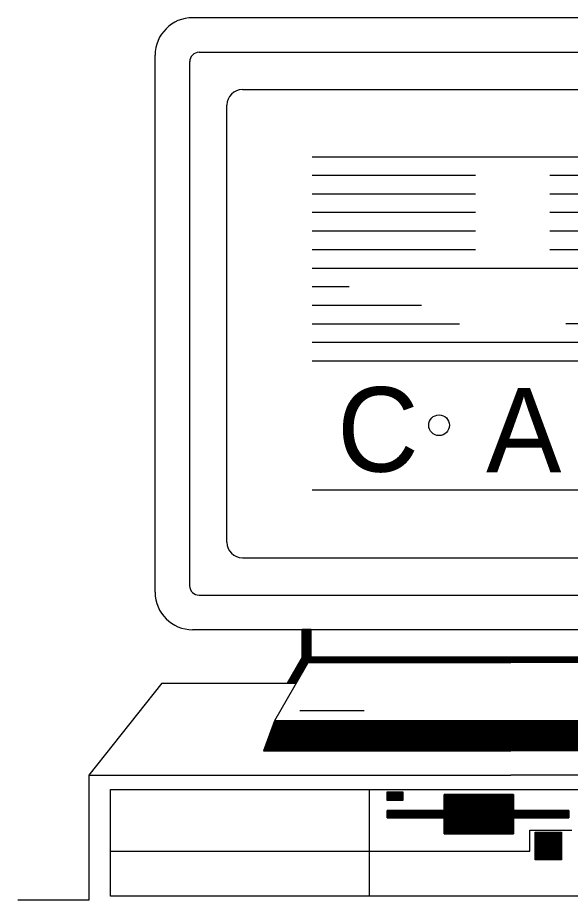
# Model space of a CAD drawing. Extents: x 22369.62 to 22376.4, y 22369.62 to 22372.46.
# Drawn here: x 22372.8189 to 22372.9001, y 22369.7337 to 22369.8633 of the extents above; entities that cross this region are included whole.
import ezdxf

# ---------------------------------------------------------------- set-up
doc = ezdxf.new("R2010")
doc.units = 0
for name, color, linetype in [('Level 2', 7, 'Continuous'), ('Level 25', 7, 'Continuous'), ('Level 3', 7, 'Continuous'), ('Level 5', 7, 'Continuous')]:
    doc.layers.add(name, color=color, linetype=linetype)

msp = doc.modelspace()

# ---------------------------------------------------------------- linework, layer by layer
at = {"layer": 'Level 2'}
for p, q in [((22372.85196, 22369.85273), (22372.93081, 22369.85273)), ((22372.84966, 22369.78628), (22372.84966, 22369.85044)), ((22372.85196, 22369.78399), (22372.93081, 22369.78399)), ((22372.86072, 22369.77334), (22372.86204, 22369.77334)), ((22372.86072, 22369.77327), (22372.86204, 22369.77327)), ((22372.86072, 22369.77318), (22372.86204, 22369.77318)), ((22372.86072, 22369.77309), (22372.86204, 22369.77309)), ((22372.86072, 22369.77301), (22372.86204, 22369.77301)), ((22372.86072, 22369.77294), (22372.86204, 22369.77294)), ((22372.86072, 22369.77285), (22372.86204, 22369.77285)), ((22372.86072, 22369.77276), (22372.86204, 22369.77276)), ((22372.86072, 22369.77268), (22372.86204, 22369.77268)), ((22372.86072, 22369.7726), (22372.86204, 22369.7726)), ((22372.86072, 22369.77252), (22372.86204, 22369.77252)), ((22372.86072, 22369.77244), (22372.86204, 22369.77244)), ((22372.86204, 22369.76941), (22372.86204, 22369.77346)), ((22372.86072, 22369.77235), (22372.86204, 22369.77235)), ((22372.86072, 22369.77227), (22372.86204, 22369.77227)), ((22372.86072, 22369.77219), (22372.86204, 22369.77219)), ((22372.86072, 22369.7721), (22372.86204, 22369.7721)), ((22372.86072, 22369.77203), (22372.86204, 22369.77203)), ((22372.86072, 22369.77194), (22372.86204, 22369.77194)), ((22372.86072, 22369.77185), (22372.86204, 22369.77185)), ((22372.86072, 22369.77178), (22372.86204, 22369.77178)), ((22372.86072, 22369.7717), (22372.86204, 22369.7717)), ((22372.86072, 22369.77161), (22372.86204, 22369.77161)), ((22372.86072, 22369.77152), (22372.86204, 22369.77152)), ((22372.86072, 22369.77145), (22372.86204, 22369.77145)), ((22372.86072, 22369.77136), (22372.86204, 22369.77136)), ((22372.86072, 22369.77128), (22372.86204, 22369.77128)), ((22372.86072, 22369.77121), (22372.86204, 22369.77121)), ((22372.86072, 22369.77111), (22372.86204, 22369.77111)), ((22372.86072, 22369.77103), (22372.86204, 22369.77103)), ((22372.86072, 22369.77095), (22372.86204, 22369.77095)), ((22372.86072, 22369.77087), (22372.86204, 22369.77087)), ((22372.86072, 22369.77079), (22372.86204, 22369.77079)), ((22372.86072, 22369.7707), (22372.86204, 22369.7707)), ((22372.86072, 22369.77061), (22372.86204, 22369.77061)), ((22372.86072, 22369.77054), (22372.86204, 22369.77054)), ((22372.86072, 22369.77046), (22372.86204, 22369.77046)), ((22372.86072, 22369.77037), (22372.86204, 22369.77037)), ((22372.86072, 22369.77029), (22372.86204, 22369.77029)), ((22372.86072, 22369.77021), (22372.86204, 22369.77021)), ((22372.86072, 22369.77012), (22372.86204, 22369.77012)), ((22372.86072, 22369.77004), (22372.86204, 22369.77004)), ((22372.86072, 22369.76997), (22372.86204, 22369.76997)), ((22372.86072, 22369.76987), (22372.86204, 22369.76987)), ((22372.86072, 22369.76979), (22372.86204, 22369.76979)), ((22372.86204, 22369.76941), (22372.85668, 22369.76007)), ((22372.86023, 22369.76855), (22372.86155, 22369.76855)), ((22372.86027, 22369.76863), (22372.86159, 22369.76863)), ((22372.86032, 22369.76873), (22372.86163, 22369.76873)), ((22372.86036, 22369.76881), (22372.86169, 22369.76881)), ((22372.86041, 22369.76888), (22372.86174, 22369.76888)), ((22372.86047, 22369.76897), (22372.86179, 22369.76897)), ((22372.86052, 22369.76905), (22372.86183, 22369.76905)), ((22372.86056, 22369.76914), (22372.86187, 22369.76914)), ((22372.8606, 22369.76922), (22372.86193, 22369.76922)), ((22372.86065, 22369.7693), (22372.86197, 22369.7693)), ((22372.8607, 22369.76938), (22372.86202, 22369.76938)), ((22372.86072, 22369.76972), (22372.86204, 22369.76972)), ((22372.86072, 22369.76963), (22372.86204, 22369.76963)), ((22372.86072, 22369.76955), (22372.86204, 22369.76955)), ((22372.86072, 22369.76946), (22372.86204, 22369.76946)), ((22372.86159, 22369.76863), (22372.89138, 22369.76863)), ((22372.8616, 22369.76864), (22372.89138, 22369.76864)), ((22372.86164, 22369.76873), (22372.89138, 22369.76873)), ((22372.8617, 22369.76882), (22372.89138, 22369.76882)), ((22372.86174, 22369.76889), (22372.89138, 22369.76889)), ((22372.86179, 22369.76898), (22372.89138, 22369.76898)), ((22372.86183, 22369.76906), (22372.89138, 22369.76906)), ((22372.86187, 22369.76914), (22372.89138, 22369.76914)), ((22372.86194, 22369.76923), (22372.89138, 22369.76923)), ((22372.86198, 22369.76931), (22372.89138, 22369.76931)), ((22372.86203, 22369.76939), (22372.89138, 22369.76939)), ((22372.86204, 22369.76941), (22372.89138, 22369.76941)), ((22372.92074, 22369.76939), (22372.89138, 22369.76939)), ((22372.92079, 22369.76931), (22372.89138, 22369.76931)), ((22372.92083, 22369.76923), (22372.89138, 22369.76923)), ((22372.92087, 22369.76914), (22372.89138, 22369.76914)), ((22372.92093, 22369.76906), (22372.89138, 22369.76906)), ((22372.92097, 22369.76898), (22372.89138, 22369.76898)), ((22372.92102, 22369.76889), (22372.89138, 22369.76889)), ((22372.92107, 22369.76882), (22372.89138, 22369.76882)), ((22372.92112, 22369.76873), (22372.89138, 22369.76873)), ((22372.92116, 22369.76864), (22372.89138, 22369.76864)), ((22372.92118, 22369.76863), (22372.89138, 22369.76863)), ((22372.85948, 22369.76724), (22372.86079, 22369.76724)), ((22372.85952, 22369.76732), (22372.86083, 22369.76732)), ((22372.85956, 22369.76739), (22372.86088, 22369.76739)), ((22372.85961, 22369.76749), (22372.86093, 22369.76749)), ((22372.85965, 22369.76757), (22372.86099, 22369.76757)), ((22372.85971, 22369.76765), (22372.86102, 22369.76765)), ((22372.85975, 22369.76773), (22372.86107, 22369.76773)), ((22372.8598, 22369.76781), (22372.86112, 22369.76781)), ((22372.85985, 22369.7679), (22372.86116, 22369.7679)), ((22372.85989, 22369.76798), (22372.86122, 22369.76798)), ((22372.85995, 22369.76806), (22372.86126, 22369.76806)), ((22372.85999, 22369.76814), (22372.8613, 22369.76814)), ((22372.86003, 22369.76823), (22372.86136, 22369.76823)), ((22372.86009, 22369.76831), (22372.8614, 22369.76831)), ((22372.86012, 22369.76839), (22372.86146, 22369.76839)), ((22372.86019, 22369.76848), (22372.8615, 22369.76848)), ((22372.85872, 22369.76591), (22372.86003, 22369.76591)), ((22372.85876, 22369.766), (22372.86008, 22369.766)), ((22372.85881, 22369.76608), (22372.86012, 22369.76608)), ((22372.85885, 22369.76616), (22372.86018, 22369.76616)), ((22372.8589, 22369.76625), (22372.86022, 22369.76625)), ((22372.85895, 22369.76633), (22372.86026, 22369.76633)), ((22372.85899, 22369.76641), (22372.86032, 22369.76641)), ((22372.85904, 22369.76649), (22372.86036, 22369.76649)), ((22372.85909, 22369.76657), (22372.86041, 22369.76657)), ((22372.85914, 22369.76666), (22372.86046, 22369.76666)), ((22372.85919, 22369.76675), (22372.8605, 22369.76675)), ((22372.85923, 22369.76682), (22372.86055, 22369.76682)), ((22372.85928, 22369.7669), (22372.86059, 22369.7669)), ((22372.85932, 22369.76699), (22372.86064, 22369.76699)), ((22372.85937, 22369.76708), (22372.8607, 22369.76708)), ((22372.85943, 22369.76715), (22372.86075, 22369.76715)), ((22372.85857, 22369.76566), (22372.85988, 22369.76566)), ((22372.85861, 22369.76575), (22372.85994, 22369.76575)), ((22372.85865, 22369.76584), (22372.85999, 22369.76584)), ((22372.85646, 22369.75947), (22372.89138, 22369.75947)), ((22372.85648, 22369.75955), (22372.89138, 22369.75955)), ((22372.85652, 22369.75963), (22372.89138, 22369.75963)), ((22372.85655, 22369.75971), (22372.89138, 22369.75971)), ((22372.85657, 22369.75979), (22372.89138, 22369.75979)), ((22372.85661, 22369.75988), (22372.89138, 22369.75988)), ((22372.85664, 22369.75996), (22372.89138, 22369.75996)), ((22372.85666, 22369.76004), (22372.89138, 22369.76004)), ((22372.85668, 22369.76007), (22372.89138, 22369.76007)), ((22372.92608, 22369.76007), (22372.89138, 22369.76007)), ((22372.92609, 22369.76004), (22372.89138, 22369.76004)), ((22372.92612, 22369.75996), (22372.89138, 22369.75996)), ((22372.92616, 22369.75988), (22372.89138, 22369.75988)), ((22372.92619, 22369.75979), (22372.89138, 22369.75979)), ((22372.92622, 22369.75971), (22372.89138, 22369.75971)), ((22372.92625, 22369.75963), (22372.89138, 22369.75963)), ((22372.92628, 22369.75955), (22372.89138, 22369.75955)), ((22372.92631, 22369.75947), (22372.89138, 22369.75947)), ((22372.85597, 22369.75814), (22372.89138, 22369.75814)), ((22372.856, 22369.75823), (22372.89138, 22369.75823)), ((22372.85602, 22369.75831), (22372.89138, 22369.75831)), ((22372.85606, 22369.75839), (22372.89138, 22369.75839)), ((22372.85609, 22369.75847), (22372.89138, 22369.75847)), ((22372.85611, 22369.75855), (22372.89138, 22369.75855)), ((22372.85615, 22369.75864), (22372.89138, 22369.75864)), ((22372.85619, 22369.75873), (22372.89138, 22369.75873)), ((22372.85621, 22369.7588), (22372.89138, 22369.7588)), ((22372.85624, 22369.75888), (22372.89138, 22369.75888)), ((22372.85628, 22369.75897), (22372.89138, 22369.75897)), ((22372.8563, 22369.75906), (22372.89138, 22369.75906)), ((22372.85633, 22369.75913), (22372.89138, 22369.75913)), ((22372.85636, 22369.75922), (22372.89138, 22369.75922)), ((22372.85639, 22369.7593), (22372.89138, 22369.7593)), ((22372.85643, 22369.75937), (22372.89138, 22369.75937)), ((22372.92633, 22369.75937), (22372.89138, 22369.75937)), ((22372.92636, 22369.7593), (22372.89138, 22369.7593)), ((22372.9264, 22369.75922), (22372.89138, 22369.75922)), ((22372.92644, 22369.75913), (22372.89138, 22369.75913)), ((22372.92646, 22369.75906), (22372.89138, 22369.75906)), ((22372.92649, 22369.75897), (22372.89138, 22369.75897)), ((22372.92653, 22369.75888), (22372.89138, 22369.75888)), ((22372.92655, 22369.7588), (22372.89138, 22369.7588)), ((22372.92658, 22369.75873), (22372.89138, 22369.75873)), ((22372.9266, 22369.75864), (22372.89138, 22369.75864)), ((22372.92664, 22369.75855), (22372.89138, 22369.75855)), ((22372.92668, 22369.75847), (22372.89138, 22369.75847)), ((22372.92671, 22369.75839), (22372.89138, 22369.75839)), ((22372.92674, 22369.75831), (22372.89138, 22369.75831)), ((22372.92677, 22369.75823), (22372.89138, 22369.75823)), ((22372.92679, 22369.75814), (22372.89138, 22369.75814)), ((22372.85551, 22369.7569), (22372.89138, 22369.7569)), ((22372.85554, 22369.757), (22372.89138, 22369.757)), ((22372.85556, 22369.75707), (22372.89138, 22369.75707)), ((22372.8556, 22369.75715), (22372.89138, 22369.75715)), ((22372.85563, 22369.75724), (22372.89138, 22369.75724)), ((22372.85565, 22369.75731), (22372.89138, 22369.75731)), ((22372.8557, 22369.7574), (22372.89138, 22369.7574)), ((22372.85573, 22369.75749), (22372.89138, 22369.75749)), ((22372.85576, 22369.75757), (22372.89138, 22369.75757)), ((22372.85578, 22369.75764), (22372.89138, 22369.75764)), ((22372.85582, 22369.75773), (22372.89138, 22369.75773)), ((22372.85584, 22369.75782), (22372.89138, 22369.75782)), ((22372.85587, 22369.75789), (22372.89138, 22369.75789)), ((22372.8559, 22369.75798), (22372.89138, 22369.75798)), ((22372.85594, 22369.75806), (22372.89138, 22369.75806)), ((22372.92682, 22369.75806), (22372.89138, 22369.75806)), ((22372.92686, 22369.75798), (22372.89138, 22369.75798)), ((22372.92688, 22369.75789), (22372.89138, 22369.75789)), ((22372.92691, 22369.75782), (22372.89138, 22369.75782)), ((22372.92695, 22369.75773), (22372.89138, 22369.75773)), ((22372.92699, 22369.75764), (22372.89138, 22369.75764)), ((22372.92701, 22369.75757), (22372.89138, 22369.75757)), ((22372.92704, 22369.75749), (22372.89138, 22369.75749)), ((22372.92706, 22369.7574), (22372.89138, 22369.7574)), ((22372.9271, 22369.75731), (22372.89138, 22369.75731)), ((22372.92713, 22369.75724), (22372.89138, 22369.75724)), ((22372.92715, 22369.75715), (22372.89138, 22369.75715)), ((22372.9272, 22369.75707), (22372.89138, 22369.75707)), ((22372.92723, 22369.757), (22372.89138, 22369.757)), ((22372.92725, 22369.7569), (22372.89138, 22369.7569)), ((22372.85506, 22369.75569), (22372.89138, 22369.75569)), ((22372.85508, 22369.75576), (22372.89138, 22369.75576)), ((22372.8551, 22369.75583), (22372.89138, 22369.75583)), ((22372.85514, 22369.75591), (22372.89138, 22369.75591)), ((22372.85518, 22369.756), (22372.89138, 22369.756)), ((22372.85521, 22369.75608), (22372.89138, 22369.75608)), ((22372.85524, 22369.75616), (22372.89138, 22369.75616)), ((22372.85527, 22369.75625), (22372.89138, 22369.75625)), ((22372.85529, 22369.75633), (22372.89138, 22369.75633)), ((22372.85532, 22369.7564), (22372.89138, 22369.7564)), ((22372.85536, 22369.75649), (22372.89138, 22369.75649)), ((22372.85538, 22369.75658), (22372.89138, 22369.75658)), ((22372.85541, 22369.75666), (22372.89138, 22369.75666)), ((22372.85545, 22369.75674), (22372.89138, 22369.75674)), ((22372.85549, 22369.75682), (22372.89138, 22369.75682)), ((22372.92728, 22369.75682), (22372.89138, 22369.75682)), ((22372.92732, 22369.75674), (22372.89138, 22369.75674)), ((22372.92734, 22369.75666), (22372.89138, 22369.75666)), ((22372.92737, 22369.75658), (22372.89138, 22369.75658)), ((22372.9274, 22369.75649), (22372.89138, 22369.75649)), ((22372.92744, 22369.7564), (22372.89138, 22369.7564)), ((22372.92747, 22369.75633), (22372.89138, 22369.75633)), ((22372.9275, 22369.75625), (22372.89138, 22369.75625)), ((22372.92752, 22369.75616), (22372.89138, 22369.75616)), ((22372.92756, 22369.75608), (22372.89138, 22369.75608)), ((22372.92759, 22369.756), (22372.89138, 22369.756)), ((22372.92761, 22369.75591), (22372.89138, 22369.75591)), ((22372.92765, 22369.75583), (22372.89138, 22369.75583)), ((22372.92769, 22369.75576), (22372.89138, 22369.75576)), ((22372.92771, 22369.75569), (22372.89138, 22369.75569)), ((22372.87063, 22369.73434), (22372.87063, 22369.75002)), ((22372.87319, 22369.74966), (22372.8755, 22369.74966)), ((22372.87319, 22369.74958), (22372.8755, 22369.74958)), ((22372.87319, 22369.74949), (22372.8755, 22369.74949)), ((22372.87319, 22369.7494), (22372.8755, 22369.7494)), ((22372.87319, 22369.74933), (22372.8755, 22369.74933)), ((22372.87319, 22369.74925), (22372.8755, 22369.74925)), ((22372.87319, 22369.74916), (22372.8755, 22369.74916)), ((22372.87319, 22369.74907), (22372.8755, 22369.74907)), ((22372.88158, 22369.74927), (22372.89176, 22369.74927)), ((22372.88158, 22369.74918), (22372.89176, 22369.74918)), ((22372.88158, 22369.7491), (22372.89176, 22369.7491)), ((22372.87319, 22369.749), (22372.8755, 22369.749)), ((22372.87319, 22369.74891), (22372.8755, 22369.74891)), ((22372.87319, 22369.74883), (22372.8755, 22369.74883)), ((22372.87319, 22369.74876), (22372.8755, 22369.74876)), ((22372.87319, 22369.74866), (22372.8755, 22369.74866)), ((22372.87319, 22369.74858), (22372.8755, 22369.74858)), ((22372.87319, 22369.7485), (22372.8755, 22369.7485)), ((22372.87319, 22369.74843), (22372.8755, 22369.74843)), ((22372.88158, 22369.74902), (22372.89176, 22369.74902)), ((22372.88158, 22369.74894), (22372.89176, 22369.74894)), ((22372.88158, 22369.74886), (22372.89176, 22369.74886)), ((22372.88158, 22369.74877), (22372.89176, 22369.74877)), ((22372.88158, 22369.74869), (22372.89176, 22369.74869)), ((22372.88158, 22369.7486), (22372.89176, 22369.7486)), ((22372.88158, 22369.74853), (22372.89176, 22369.74853)), ((22372.88158, 22369.74845), (22372.89176, 22369.74845)), ((22372.88158, 22369.74835), (22372.89176, 22369.74835)), ((22372.88158, 22369.74827), (22372.89176, 22369.74827)), ((22372.88158, 22369.7482), (22372.89176, 22369.7482)), ((22372.88158, 22369.74811), (22372.89176, 22369.74811)), ((22372.88158, 22369.74803), (22372.89176, 22369.74803)), ((22372.88158, 22369.74795), (22372.89176, 22369.74795)), ((22372.88158, 22369.74786), (22372.89176, 22369.74786)), ((22372.88158, 22369.74778), (22372.89176, 22369.74778)), ((22372.87322, 22369.74687), (22372.89989, 22369.74687)), ((22372.87322, 22369.7468), (22372.89989, 22369.7468)), ((22372.87322, 22369.74671), (22372.89989, 22369.74671)), ((22372.87322, 22369.74662), (22372.89989, 22369.74662)), ((22372.87322, 22369.74654), (22372.89989, 22369.74654)), ((22372.88158, 22369.7477), (22372.89176, 22369.7477)), ((22372.88158, 22369.74762), (22372.89176, 22369.74762)), ((22372.88158, 22369.74753), (22372.89176, 22369.74753)), ((22372.88158, 22369.74745), (22372.89176, 22369.74745)), ((22372.88158, 22369.74737), (22372.89176, 22369.74737)), ((22372.88158, 22369.74729), (22372.89176, 22369.74729)), ((22372.88158, 22369.74721), (22372.89176, 22369.74721)), ((22372.88158, 22369.74711), (22372.89176, 22369.74711)), ((22372.88158, 22369.74704), (22372.89176, 22369.74704)), ((22372.88158, 22369.74696), (22372.89176, 22369.74696)), ((22372.87322, 22369.74647), (22372.89989, 22369.74647)), ((22372.87322, 22369.74638), (22372.89989, 22369.74638)), ((22372.87322, 22369.74629), (22372.89989, 22369.74629)), ((22372.87322, 22369.74621), (22372.89989, 22369.74621)), ((22372.87322, 22369.74613), (22372.89989, 22369.74613)), ((22372.87322, 22369.74605), (22372.89989, 22369.74605)), ((22372.87322, 22369.74597), (22372.89989, 22369.74597)), ((22372.87322, 22369.74588), (22372.89989, 22369.74588)), ((22372.88158, 22369.7458), (22372.89176, 22369.7458)), ((22372.88158, 22369.74572), (22372.89176, 22369.74572)), ((22372.88158, 22369.74563), (22372.89176, 22369.74563)), ((22372.88158, 22369.74556), (22372.89176, 22369.74556)), ((22372.88158, 22369.74547), (22372.89176, 22369.74547)), ((22372.88158, 22369.74538), (22372.89176, 22369.74538)), ((22372.88158, 22369.74531), (22372.89176, 22369.74531)), ((22372.88158, 22369.74523), (22372.89176, 22369.74523)), ((22372.88158, 22369.74514), (22372.89176, 22369.74514)), ((22372.88158, 22369.74505), (22372.89176, 22369.74505)), ((22372.88158, 22369.74498), (22372.89176, 22369.74498)), ((22372.88158, 22369.74489), (22372.89176, 22369.74489)), ((22372.88158, 22369.74481), (22372.89176, 22369.74481)), ((22372.88158, 22369.74474), (22372.89176, 22369.74474)), ((22372.88158, 22369.74464), (22372.89176, 22369.74464)), ((22372.88158, 22369.74456), (22372.89176, 22369.74456)), ((22372.88158, 22369.74448), (22372.89176, 22369.74448)), ((22372.88158, 22369.7444), (22372.89176, 22369.7444)), ((22372.88158, 22369.74432), (22372.89176, 22369.74432)), ((22372.88158, 22369.74423), (22372.89176, 22369.74423)), ((22372.88158, 22369.74414), (22372.89176, 22369.74414)), ((22372.88158, 22369.74407), (22372.89176, 22369.74407)), ((22372.88158, 22369.74399), (22372.89176, 22369.74399)), ((22372.88158, 22369.7439), (22372.89176, 22369.7439)), ((22372.89418, 22369.74403), (22372.90035, 22369.74403)), ((22372.89418, 22369.74094), (22372.89418, 22369.74403)), ((22372.88158, 22369.74382), (22372.89176, 22369.74382)), ((22372.88158, 22369.74374), (22372.89176, 22369.74374)), ((22372.88158, 22369.74365), (22372.89176, 22369.74365)), ((22372.88158, 22369.74357), (22372.89176, 22369.74357)), ((22372.89496, 22369.74365), (22372.89884, 22369.74365)), ((22372.89496, 22369.74357), (22372.89884, 22369.74357)), ((22372.89496, 22369.7435), (22372.89884, 22369.7435)), ((22372.89496, 22369.74341), (22372.89884, 22369.74341)), ((22372.89496, 22369.74332), (22372.89884, 22369.74332)), ((22372.89496, 22369.74325), (22372.89884, 22369.74325)), ((22372.89496, 22369.74316), (22372.89884, 22369.74316)), ((22372.89496, 22369.74308), (22372.89884, 22369.74308)), ((22372.89496, 22369.743), (22372.89884, 22369.743)), ((22372.89496, 22369.74291), (22372.89884, 22369.74291)), ((22372.89496, 22369.74283), (22372.89884, 22369.74283)), ((22372.89496, 22369.74275), (22372.89884, 22369.74275)), ((22372.89496, 22369.74268), (22372.89884, 22369.74268)), ((22372.89496, 22369.74259), (22372.89884, 22369.74259)), ((22372.89496, 22369.7425), (22372.89884, 22369.7425)), ((22372.89496, 22369.74241), (22372.89884, 22369.74241)), ((22372.89496, 22369.74234), (22372.89884, 22369.74234)), ((22372.89496, 22369.74226), (22372.89884, 22369.74226)), ((22372.89496, 22369.74218), (22372.89884, 22369.74218)), ((22372.89496, 22369.74208), (22372.89884, 22369.74208)), ((22372.89496, 22369.74201), (22372.89884, 22369.74201)), ((22372.89496, 22369.74193), (22372.89884, 22369.74193)), ((22372.89496, 22369.74184), (22372.89884, 22369.74184)), ((22372.89496, 22369.74177), (22372.89884, 22369.74177)), ((22372.89496, 22369.74168), (22372.89884, 22369.74168)), ((22372.89496, 22369.74159), (22372.89884, 22369.74159)), ((22372.89496, 22369.74151), (22372.89884, 22369.74151)), ((22372.89496, 22369.74144), (22372.89884, 22369.74144)), ((22372.89496, 22369.74135), (22372.89884, 22369.74135)), ((22372.8326, 22369.74094), (22372.89418, 22369.74094)), ((22372.89496, 22369.74126), (22372.89884, 22369.74126)), ((22372.89496, 22369.74119), (22372.89884, 22369.74119)), ((22372.89496, 22369.7411), (22372.89884, 22369.7411)), ((22372.89496, 22369.74102), (22372.89884, 22369.74102)), ((22372.89496, 22369.74094), (22372.89884, 22369.74094)), ((22372.89496, 22369.74085), (22372.89884, 22369.74085)), ((22372.89496, 22369.74077), (22372.89884, 22369.74077)), ((22372.89496, 22369.74069), (22372.89884, 22369.74069)), ((22372.89496, 22369.74061), (22372.89884, 22369.74061)), ((22372.89496, 22369.74053), (22372.89884, 22369.74053)), ((22372.89496, 22369.74044), (22372.89884, 22369.74044)), ((22372.89496, 22369.74035), (22372.89884, 22369.74035)), ((22372.89496, 22369.74028), (22372.89884, 22369.74028)), ((22372.89496, 22369.7402), (22372.89884, 22369.7402)), ((22372.89496, 22369.74011), (22372.89884, 22369.74011)), ((22372.89496, 22369.74002), (22372.89884, 22369.74002)), ((22372.89496, 22369.73995), (22372.89884, 22369.73995)), ((22372.89496, 22369.73986), (22372.89884, 22369.73986)), ((22372.89496, 22369.73978), (22372.89884, 22369.73978)), ((22372.89496, 22369.73971), (22372.89884, 22369.73971))]:
    msp.add_line(p, q, dxfattribs=at)
for points in [[(22372.86072, 22369.77346), (22372.86072, 22369.76941), (22372.85852, 22369.7656), (22372.85985, 22369.7656), (22372.86204, 22369.76941), (22372.86204, 22369.77346)], [(22372.86204, 22369.76941), (22372.86159, 22369.76863), (22372.89138, 22369.76863), (22372.89138, 22369.76941)], [(22372.92072, 22369.76941), (22372.92118, 22369.76863), (22372.89138, 22369.76863), (22372.89138, 22369.76941)], [(22372.85668, 22369.76007), (22372.85506, 22369.75569), (22372.89138, 22369.75569), (22372.89138, 22369.76007)], [(22372.92608, 22369.76007), (22372.92771, 22369.75569), (22372.89138, 22369.75569), (22372.89138, 22369.76007)], [(22372.8326, 22369.75002), (22372.95035, 22369.75002), (22372.95035, 22369.73434), (22372.8326, 22369.73434)], [(22372.87319, 22369.74968), (22372.8755, 22369.74968), (22372.8755, 22369.74838), (22372.87319, 22369.74838)], [(22372.88158, 22369.74928), (22372.88158, 22369.74694), (22372.87322, 22369.74694), (22372.87322, 22369.74585), (22372.88158, 22369.74585), (22372.88158, 22369.74352), (22372.89176, 22369.74352), (22372.89176, 22369.74585), (22372.89989, 22369.74585), (22372.89989, 22369.74694), (22372.89176, 22369.74694), (22372.89176, 22369.74928)], [(22372.89496, 22369.74372), (22372.89884, 22369.74372), (22372.89884, 22369.73968), (22372.89496, 22369.73968)]]:
    msp.add_lwpolyline(points, close=True, dxfattribs=at)
for points in [[(22372.88158, 22369.74694), (22372.88158, 22369.74928), (22372.89176, 22369.74928), (22372.89176, 22369.74694)], [(22372.88158, 22369.74585), (22372.87322, 22369.74585), (22372.87322, 22369.74694), (22372.88158, 22369.74694)], [(22372.89176, 22369.74694), (22372.89989, 22369.74694), (22372.89989, 22369.74585), (22372.89176, 22369.74585)], [(22372.89176, 22369.74585), (22372.89176, 22369.74352), (22372.88158, 22369.74352), (22372.88158, 22369.74585)]]:
    msp.add_lwpolyline(points, dxfattribs=at)
msp.add_circle((22372.88084, 22369.80345), 0.00152, dxfattribs=at)
for centre, start, end in [((22372.85196, 22369.85043), 90, 180), ((22372.85196, 22369.78628), 180, 270)]:
    msp.add_arc(centre, 0.00229, start, end, dxfattribs=at)
at = {"layer": 'Level 25'}
for p, q in [((22372.86072, 22369.77343), (22372.86204, 22369.77343)), ((22372.92072, 22369.76941), (22372.89138, 22369.76941)), ((22372.85668, 22369.76007), (22372.85506, 22369.75569))]:
    msp.add_line(p, q, dxfattribs=at)
at = {"layer": 'Level 3'}
for p, q in [((22372.84463, 22369.86326), (22372.93813, 22369.86326)), ((22372.84558, 22369.85819), (22372.93709, 22369.85819)), ((22372.83913, 22369.77896), (22372.83913, 22369.85776)), ((22372.84421, 22369.77991), (22372.84421, 22369.85681)), ((22372.84558, 22369.77854), (22372.93709, 22369.77854)), ((22372.84463, 22369.77346), (22372.93813, 22369.77346))]:
    msp.add_line(p, q, dxfattribs=at)
for centre, radius, start, end in [((22372.84463, 22369.85775), 0.0055, 90, 180), ((22372.84558, 22369.8568), 0.00137, 90, 180), ((22372.84463, 22369.77895), 0.0055, 180, 270), ((22372.84558, 22369.7799), 0.00138, 180, 270)]:
    msp.add_arc(centre, radius, start, end, dxfattribs=at)
at = {"layer": 'Level 5'}
for p, q in [((22372.86218, 22369.84286), (22372.92113, 22369.84286)), ((22372.86218, 22369.84013), (22372.88621, 22369.84013)), ((22372.89709, 22369.84013), (22372.92113, 22369.84013)), ((22372.86218, 22369.83741), (22372.88621, 22369.83741)), ((22372.89709, 22369.83741), (22372.92113, 22369.83741)), ((22372.86218, 22369.8347), (22372.88621, 22369.8347)), ((22372.89709, 22369.8347), (22372.92113, 22369.8347)), ((22372.86218, 22369.83197), (22372.88621, 22369.83197)), ((22372.89709, 22369.83197), (22372.92113, 22369.83197)), ((22372.86218, 22369.82924), (22372.88621, 22369.82924)), ((22372.89709, 22369.82924), (22372.92113, 22369.82924)), ((22372.86218, 22369.82651), (22372.92113, 22369.82651)), ((22372.86218, 22369.8238), (22372.86762, 22369.8238)), ((22372.86218, 22369.82107), (22372.87824, 22369.82107)), ((22372.86218, 22369.81835), (22372.88382, 22369.81835)), ((22372.92112, 22369.81835), (22372.89948, 22369.81835)), ((22372.86218, 22369.81562), (22372.92113, 22369.81562)), ((22372.86218, 22369.81289), (22372.92113, 22369.81289)), ((22372.86218, 22369.79399), (22372.92124, 22369.79399)), ((22372.86072, 22369.76941), (22372.86072, 22369.77346)), ((22372.86072, 22369.76941), (22372.85852, 22369.7656)), ((22372.84011, 22369.7656), (22372.8294, 22369.75209)), ((22372.84011, 22369.7656), (22372.85985, 22369.7656)), ((22372.86037, 22369.7616), (22372.86984, 22369.7616)), ((22372.8294, 22369.75209), (22372.8294, 22369.73374)), ((22372.8294, 22369.75209), (22372.89138, 22369.75209)), ((22372.95335, 22369.75209), (22372.89138, 22369.75209)), ((22372.8294, 22369.73374), (22372.81894, 22369.73374))]:
    msp.add_line(p, q, dxfattribs=at)

# ---------------------------------------------------------------- texts
for s, p in [('C', (22372.86587, 22369.79664)), ('A', (22372.88775, 22369.79654))]:
    msp.add_text(s, height=0.0124, dxfattribs=at).set_placement(p)

doc.saveas('drawing.dxf')
